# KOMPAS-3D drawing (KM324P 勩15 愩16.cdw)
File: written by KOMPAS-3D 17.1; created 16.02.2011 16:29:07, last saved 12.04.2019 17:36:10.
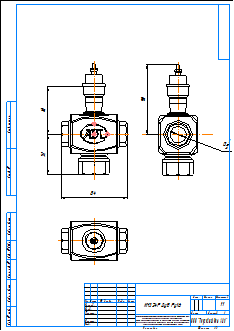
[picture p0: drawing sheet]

Title block, sheet 1: name: KM324P Ду15 Ру16; material: Внимание! Данный продукт является объектом авторского права ООО «Торговый Дом АДЛ». / Запрещается изменение, копирование, распространение / (в том числе путем копирования на другие сайты и ресурсы в Интернете) / или любое иное использование информации и объектов без предварительного / согласия правообладателя (ООО «Торговый Дом АДЛ»).; scale: 1:1; sheets: 1; organisation: ООО "Торговый дом АДЛ"; sheet format: A3; stored path: \\adlc.lan\data\АДЛ_ПКД\3D-модели\ADL production\Клапаны ГРАНРЕГ\Трёхходовой клапан KM324P\KOMPAS 2D\KM324P Ду15 Ру16.cdw

Views: Спереди 1, Проекционный вид 2, Проекционный вид 3
Dimensions and other numbers on the sheet: 84; 52; 61; 90; 1:1; 1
